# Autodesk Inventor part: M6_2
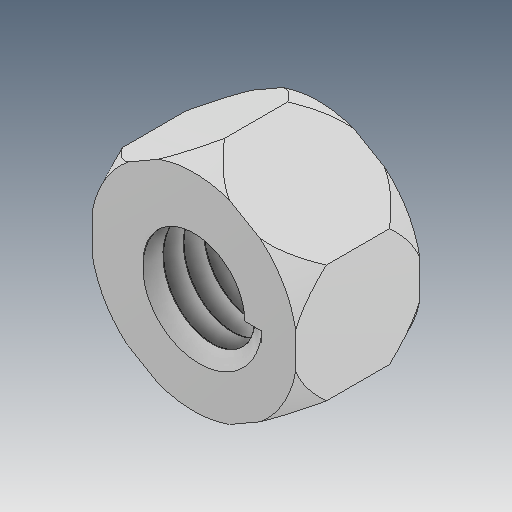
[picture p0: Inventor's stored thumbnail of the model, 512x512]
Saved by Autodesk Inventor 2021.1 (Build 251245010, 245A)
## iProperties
Created: 2021-05
Part Number: M6_2
Material: Ogólny
Document SubType Name: Modeling
Designer: user
Density: 1 g/cm^3
Appearance: Domyślna
Author: user
Revision Number: ÈÎºÎ
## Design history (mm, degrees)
feature "ÊäÈë1"
node "Bryła1"
